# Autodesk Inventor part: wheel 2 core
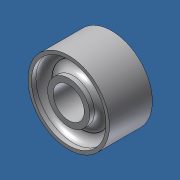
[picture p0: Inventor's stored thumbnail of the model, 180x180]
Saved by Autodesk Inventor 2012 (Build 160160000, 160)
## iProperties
Created: 2010-10
Part Number: wheel 2 core
Document SubType Name: Modeling
Designer: Administrator
Density: 1.4 g/cm^3
Material: PVC-U
Mass: 71.1734 g
Surface Area: 166.499 cm^2
Volume: 50.8382 cm^3
Author: Administrator
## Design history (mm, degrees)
feature "Base1"
body "Solid1"
